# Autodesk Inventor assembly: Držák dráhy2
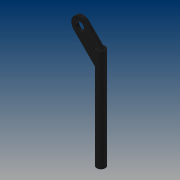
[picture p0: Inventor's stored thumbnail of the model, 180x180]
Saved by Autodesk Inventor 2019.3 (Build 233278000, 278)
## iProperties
Created: 2019-03
Part Number: Držák dráhy2
Material: Všeobecné
Document SubType Name: Assembly
Designer: B-hon
Author: B-hon
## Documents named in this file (3)
- C:\Users\B-hon\OneDrive\Plocha\Bakalářka22\Držák dráhy2.iam
- C:\Users\B-hon\OneDrive\Plocha\Bakalářka22\Tyč držáku.ipt
- C:\Users\B-hon\OneDrive\Plocha\Bakalářka22\Držák čepu2.ipt
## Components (2 placed, 2 different names)
1. Tyč držáku:1 — Proti sobě:1, Tečnost:1, Proti sobě:2
2. Držák čepu2:1 — Proti sobě:1, Tečnost:1, Proti sobě:2
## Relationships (3: Mate 2, Tangent 1)
- Proti sobě:1 [Mate]: Tyč držáku:1 ↔ Držák čepu2:1
- Tečnost:1 [Tangent]: Tyč držáku:1 ↔ Držák čepu2:1
- Proti sobě:2 [Mate]: Tyč držáku:1 ↔ Držák čepu2:1
